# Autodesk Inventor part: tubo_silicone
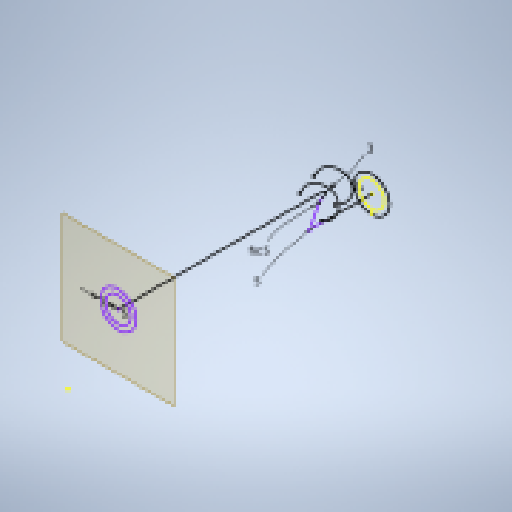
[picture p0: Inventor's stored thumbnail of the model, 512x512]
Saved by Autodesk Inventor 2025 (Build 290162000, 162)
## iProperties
Created: 2026-03
Part Number: tubo_silicone
Material: Generico
Document SubType Name: Modeling
Designer: Ryzen5700u
Density: 1 g/cm^3
Appearance: Default
Author: Ryzen5700u
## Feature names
1. Sweep1
## Parameters: d0 = 0.6 mm, d4 = 5 mm, d5 = 0.6 mm, d6 = 0, d7 = 0, d8 = 5 mm, d9 = 5 mm
